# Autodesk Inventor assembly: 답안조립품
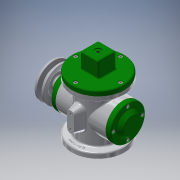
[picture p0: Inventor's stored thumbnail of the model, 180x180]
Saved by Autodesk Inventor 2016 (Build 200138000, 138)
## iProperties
Created: 2018-02
Part Number: 답안조립품
Material: 일반
Document SubType Name: Assembly
Designer: 605-15
Author: 605-15
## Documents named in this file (18)
- C:\Users\605-15\Desktop\480207V1001\답안조립품.iam
- C:\Users\605-15\Desktop\480207V1001\본체.ipt
- C:\Users\605-15\Desktop\480207V1001\E-링.ipt
- C:\Users\605-15\Desktop\480207V1001\V-벨트풀리.ipt
- C:\Users\605-15\Desktop\480207V1001\덮개.ipt
- C:\Users\605-15\Desktop\480207V1001\뒤커버.ipt
- C:\Users\605-15\Desktop\480207V1001\링크.ipt
- C:\Users\605-15\Desktop\480207V1001\베어링 17 x 40 x 12.ipt
- C:\Users\605-15\Desktop\480207V1001\볼트 M4 x 8.ipt
- C:\Users\605-15\Desktop\480207V1001\볼트 M4 x 10.ipt
- C:\Users\605-15\Desktop\480207V1001\슬라이더.ipt
- C:\Users\605-15\Desktop\480207V1001\앞커버.ipt
- C:\Users\605-15\Desktop\480207V1001\오일 실 17 30 8.ipt
- C:\Users\605-15\Desktop\480207V1001\와셔 4x16.ipt
- C:\Users\605-15\Desktop\480207V1001\클레비스 핀 6 x 22.ipt
- 클레비스 핀 6 x 22.ipt
- C:\Users\605-15\Desktop\480207V1001\키 4 x 4 x 12.ipt
- C:\Users\605-15\Desktop\480207V1001\편심축.ipt
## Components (2 placed, 2 different names)
1. E-링:1
2. V-벨트풀리:1 — 각도:1, 각도:4
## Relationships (2: Angle 2)
- 각도:1 [Angle]: V-벨트풀리:1
- 각도:4 [Angle]: V-벨트풀리:1
